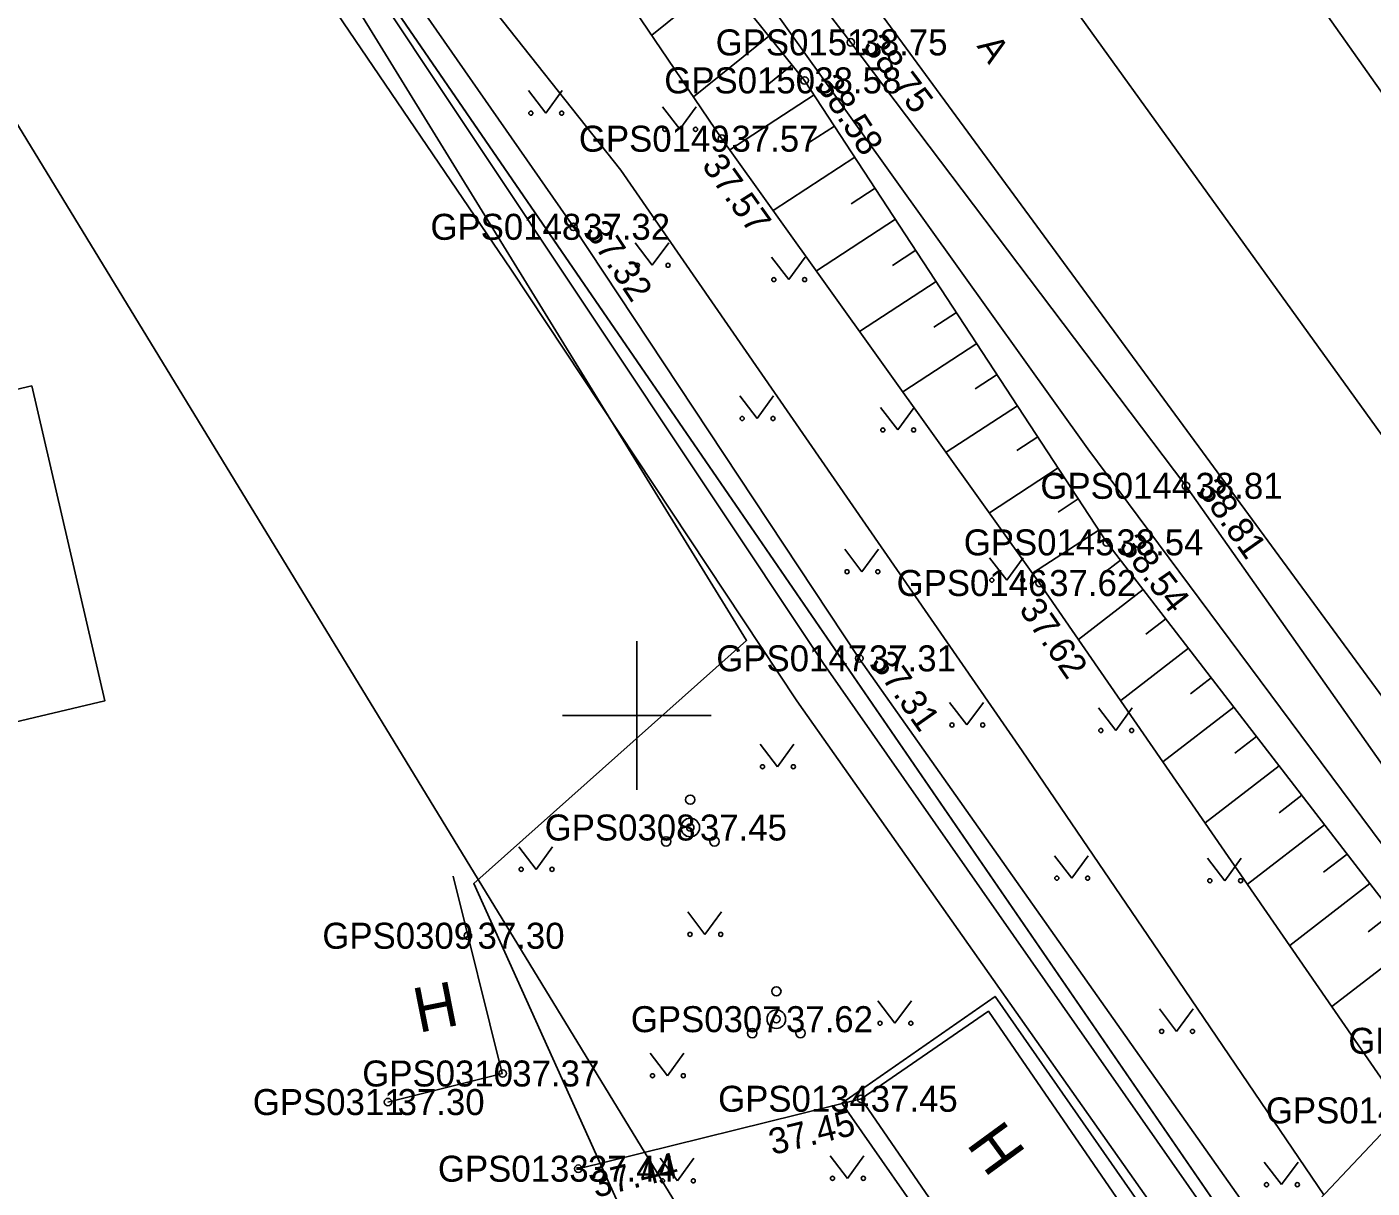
# Model space of a CAD drawing. Extents: x 626224 to 628280, y 6467750 to 6471135.
# Drawn here: x 627683.58 to 627719.8, y 6468587.27 to 6468618.54 of the extents above; entities that cross this region are included whole.
import ezdxf

# ---------------------------------------------------------------- set-up
doc = ezdxf.new("R2010")
doc.units = 0
for name, color, linetype in [('AED', 7, 'Continuous'), ('HALJASTUS', 7, 'Continuous'), ('HOONE', 7, 'Continuous'), ('Hoone Elu- või ühiskondlik hoone', 7, 'Continuous'), ('KORGUS-EH2000', 7, 'Continuous'), ('MOOTKORG-EH2000', 7, 'Continuous'), ('MOOTMPUNKT', 7, 'Continuous'), ('MOOTNR', 7, 'Continuous'), ('MOOTPIIR', 7, 'Continuous'), ('MPOHULIIN', 7, 'Continuous'), ('Muu rajatis Katusealune', 7, 'Continuous'), ('PIIR', 7, 'Continuous'), ('PUU', 7, 'Continuous'), ('RELJEEF', 7, 'Continuous'), ('SITRASS', 7, 'Continuous'), ('TEE', 7, 'Continuous'), ('Tee Liiklusala', 7, 'Continuous'), ('Tee Põhimaantee Püsikate', 7, 'Continuous'), ('VORK', 7, 'Continuous')]:
    doc.layers.add(name, color=color, linetype=linetype)

msp = doc.modelspace()

# ---------------------------------------------------------------- linework, layer by layer
at = {"layer": 'AED'}
msp.add_line((627706.037, 6468589.677), (627698.423, 6468587.794), dxfattribs=at)
at = {"layer": 'HALJASTUS'}
for p, q in [((627697.083, 6468616.826), (627697.547, 6468616.219)), ((627697.547, 6468616.219), (627697.992, 6468616.826)), ((627700.689, 6468616.392), (627701.153, 6468615.785)), ((627701.153, 6468615.785), (627701.598, 6468616.392)), ((627699.95, 6468612.729), (627700.413, 6468612.123)), ((627700.413, 6468612.123), (627700.859, 6468612.729)), ((627703.625, 6468612.345), (627704.088, 6468611.738)), ((627704.088, 6468611.738), (627704.534, 6468612.345)), ((627702.774, 6468608.603), (627703.237, 6468607.996)), ((627703.237, 6468607.996), (627703.683, 6468608.603)), ((627706.56, 6468608.297), (627707.024, 6468607.69)), ((627707.024, 6468607.69), (627707.469, 6468608.297)), ((627705.598, 6468604.477), (627706.061, 6468603.87)), ((627706.061, 6468603.87), (627706.507, 6468604.477)), ((627709.496, 6468604.249), (627709.959, 6468603.643)), ((627709.959, 6468603.643), (627710.405, 6468604.249)), ((627708.421, 6468600.351), (627708.885, 6468599.744)), ((627708.885, 6468599.744), (627709.33, 6468600.351)), ((627712.431, 6468600.202), (627712.895, 6468599.595)), ((627712.895, 6468599.595), (627713.34, 6468600.202)), ((627703.321, 6468599.226), (627703.784, 6468598.619)), ((627703.784, 6468598.619), (627704.23, 6468599.226)), ((627696.823, 6468596.463), (627697.286, 6468595.856)), ((627697.286, 6468595.856), (627697.732, 6468596.463)), ((627711.245, 6468596.224), (627711.709, 6468595.618)), ((627711.709, 6468595.618), (627712.154, 6468596.224)), ((627715.367, 6468596.154), (627715.83, 6468595.548)), ((627715.83, 6468595.548), (627716.276, 6468596.154)), ((627701.368, 6468594.711), (627701.831, 6468594.104)), ((627701.831, 6468594.104), (627702.277, 6468594.711)), ((627706.485, 6468592.319), (627706.949, 6468591.712)), ((627706.949, 6468591.712), (627707.394, 6468592.319)), ((627714.069, 6468592.098), (627714.533, 6468591.491)), ((627714.533, 6468591.491), (627714.978, 6468592.098)), ((627700.358, 6468590.904), (627700.821, 6468590.297)), ((627700.821, 6468590.297), (627701.267, 6468590.904)), ((627700.627, 6468588.074), (627701.091, 6468587.467)), ((627701.091, 6468587.467), (627701.536, 6468588.074)), ((627705.206, 6468588.141), (627705.669, 6468587.534)), ((627705.669, 6468587.534), (627706.115, 6468588.141)), ((627716.893, 6468587.972), (627717.356, 6468587.365)), ((627717.356, 6468587.365), (627717.802, 6468587.972))]:
    msp.add_line(p, q, dxfattribs=at)
for points in [[(627673.61, 6468619.969), (627672.976, 6468621.286), (627679.187, 6468622.456), (627687.969, 6468624.157), (627689.948, 6468620.551), (627692.796, 6468621.064), (627698.292, 6468613.159), (627705.989, 6468601.538), (627717.166, 6468585.678)], [(627716.572, 6468584.873), (627705.028, 6468601.396), (627692.406, 6468620.356), (627689.621, 6468619.759), (627687.703, 6468623.543), (627673.321, 6468620.739)], [(627673.61, 6468619.969), (627679.701, 6468621.092), (627687.315, 6468622.642), (627689.297, 6468618.889), (627691.61, 6468619.392), (627696.609, 6468612.017), (627704.309, 6468600.39), (627715.503, 6468584.506)]]:
    msp.add_lwpolyline(points, dxfattribs=at)
for centre in [(627697.146, 6468616.219), (627697.975, 6468616.219), (627700.752, 6468615.785), (627701.58, 6468615.785), (627700.012, 6468612.123), (627700.841, 6468612.123), (627703.687, 6468611.738), (627704.516, 6468611.738), (627702.836, 6468607.996), (627703.665, 6468607.996), (627706.623, 6468607.69), (627707.451, 6468607.69), (627705.66, 6468603.87), (627706.489, 6468603.87), (627709.558, 6468603.643), (627710.387, 6468603.643), (627708.484, 6468599.744), (627709.313, 6468599.744), (627712.494, 6468599.595), (627713.323, 6468599.595), (627703.383, 6468598.619), (627704.212, 6468598.619), (627696.885, 6468595.856), (627697.714, 6468595.856), (627711.308, 6468595.618), (627712.137, 6468595.618), (627715.429, 6468595.548), (627716.258, 6468595.548), (627701.43, 6468594.104), (627702.259, 6468594.104), (627706.548, 6468591.712), (627707.377, 6468591.712), (627714.132, 6468591.491), (627714.96, 6468591.491), (627700.42, 6468590.297), (627701.249, 6468590.297), (627705.268, 6468587.534), (627706.097, 6468587.534), (627700.69, 6468587.467), (627701.518, 6468587.467), (627716.955, 6468587.365), (627717.784, 6468587.365)]:
    msp.add_circle(centre, 0.055, dxfattribs=at)
at = {"layer": 'HOONE'}
for p, q in [((627695.051, 6468595.673), (627696.376, 6468590.356)), ((627693.298, 6468589.589), (627696.386, 6468590.358))]:
    msp.add_line(p, q, dxfattribs=at)
msp.add_lwpolyline([(627706.037, 6468589.677), (627709.589, 6468584.515), (627713.017, 6468586.873), (627709.466, 6468592.035)], close=True, dxfattribs=at)
at = {"layer": 'Hoone Elu- või ühiskondlik hoone'}
msp.add_lwpolyline([(627678.585, 6468598.716), (627677.114, 6468604.925), (627668.925, 6468602.995), (627666.971, 6468610.855), (627681.171, 6468614.225), (627682.555, 6468608.606), (627683.705, 6468608.876), (627685.675, 6468600.395)], close=True, dxfattribs=at)
at = {"layer": 'KORGUS-EH2000'}
for centre in [(627705.762, 6468618.126), (627704.517, 6468617.101), (627702.288, 6468615.532), (627698.292, 6468613.159), (627714.785, 6468606.184), (627712.652, 6468604.661), (627710.843, 6468603.567), (627705.989, 6468601.538), (627701.438, 6468596.982), (627703.756, 6468591.821), (627696.386, 6468590.358), (627706.037, 6468589.677), (627698.423, 6468587.794)]:
    msp.add_circle(centre, 0.1, dxfattribs=at)
at = {"layer": 'MOOTMPUNKT'}
for centre in [(627705.762, 6468618.126), (627704.517, 6468617.101), (627702.288, 6468615.532), (627698.292, 6468613.159), (627714.785, 6468606.184), (627712.652, 6468604.661), (627710.843, 6468603.567), (627705.989, 6468601.538), (627701.438, 6468596.982), (627695.451, 6468594.068), (627703.756, 6468591.821), (627696.386, 6468590.358), (627706.037, 6468589.677), (627693.298, 6468589.589), (627698.423, 6468587.794)]:
    msp.add_circle(centre, 0.1, dxfattribs=at)
at = {"layer": 'MOOTPIIR'}
for points in [[(627725.17, 6468593.561), (627699.891, 6468628.007), (627691.556, 6468636.216), (627689.682, 6468635.294), (627688.429, 6468634.933), (627687.779, 6468636.161), (627663.981, 6468631.653), (627656.533, 6468628.521), (627633.238, 6468625.152)], [(627644.92, 6468614.927), (627687.389, 6468622.904), (627689.377, 6468619.311), (627692.038, 6468619.76), (627702.956, 6468602.021), (627695.606, 6468595.477), (627701.992, 6468581.333), (627711.232, 6468581.738), (627717.166, 6468585.678), (627720.646, 6468589.364)]]:
    msp.add_lwpolyline(points, dxfattribs=at)
at = {"layer": 'MPOHULIIN'}
for points in [[(627695.728, 6468595.585), (627679.915, 6468621.5)], [(627704.355, 6468581.436), (627701.716, 6468585.772), (627695.728, 6468595.585)]]:
    msp.add_lwpolyline(points, dxfattribs=at)
at = {"layer": 'Muu rajatis Katusealune'}
msp.add_lwpolyline([(627705.521, 6468589.562), (627709.645, 6468592.435), (627715.151, 6468584.531), (627711.028, 6468581.659)], close=True, dxfattribs=at)
at = {"layer": 'PIIR'}
msp.add_lwpolyline([(627746.91, 6468541.23), (627688.18, 6468626.77), (627684.35, 6468632.16), (627686.69, 6468632.75), (627663.66, 6468662.2), (627667.34, 6468664.86), (627649.05, 6468692.73), (627646.31, 6468691.19), (627629.12, 6468721.76), (627618.92, 6468715.04), (627606.91, 6468724.16), (627579.16, 6468687.58), (627549.96, 6468707.41), (627588.77, 6468756.22), (627618.05, 6468733.86), (627619.84, 6468735.06), (627604.18, 6468764.29), (627579.83, 6468812.09), (627559.2, 6468856.67), (627547.01, 6468886.57), (627533.67, 6468925.79), (627531.86, 6468935.62), (627512.37, 6469002.4)], dxfattribs=at)
msp.add_lwpolyline([(627746.91, 6468541.23), (627666.94, 6468517.08), (627653, 6468577.43), (627643.52, 6468618.24), (627688.18, 6468626.77)], close=True, dxfattribs=at)
at = {"layer": 'PUU'}
for centre, radius in [((627701.438, 6468597.732), 0.125), ((627701.438, 6468596.982), 0.25), ((627700.788, 6468596.607), 0.125), ((627702.088, 6468596.607), 0.125), ((627703.756, 6468592.571), 0.125), ((627703.756, 6468591.821), 0.25), ((627703.106, 6468591.446), 0.125), ((627704.406, 6468591.446), 0.125)]:
    msp.add_circle(centre, radius, dxfattribs=at)
at = {"layer": 'RELJEEF'}
for p, q in [((627702.302, 6468619.854), (627700.399, 6468618.322)), ((627703.556, 6468618.296), (627701.524, 6468616.66)), ((627704.183, 6468617.517), (627703.554, 6468617.011)), ((627704.773, 6468616.711), (627702.506, 6468615.228)), ((627705.32, 6468615.874), (627704.65, 6468615.436)), ((627705.868, 6468615.037), (627703.67, 6468613.6)), ((627706.415, 6468614.2), (627705.766, 6468613.776)), ((627706.962, 6468613.363), (627704.834, 6468611.972)), ((627707.509, 6468612.526), (627706.881, 6468612.115)), ((627708.057, 6468611.689), (627705.998, 6468610.343)), ((627708.604, 6468610.852), (627707.997, 6468610.455)), ((627709.151, 6468610.015), (627707.163, 6468608.715)), ((627709.698, 6468609.178), (627709.112, 6468608.795)), ((627710.246, 6468608.341), (627708.327, 6468607.087)), ((627710.793, 6468607.504), (627710.228, 6468607.135)), ((627711.34, 6468606.667), (627709.491, 6468605.458)), ((627711.887, 6468605.83), (627711.343, 6468605.474)), ((627712.435, 6468604.993), (627710.655, 6468603.83)), ((627713.02, 6468604.183), (627712.511, 6468603.79)), ((627713.631, 6468603.392), (627711.891, 6468602.049)), ((627714.242, 6468602.6), (627713.707, 6468602.188)), ((627714.853, 6468601.808), (627713.029, 6468600.401)), ((627715.464, 6468601.016), (627714.904, 6468600.585)), ((627716.074, 6468600.225), (627714.166, 6468598.753)), ((627716.685, 6468599.433), (627716.1, 6468598.982)), ((627717.296, 6468598.641), (627715.304, 6468597.104)), ((627717.907, 6468597.849), (627717.297, 6468597.379)), ((627718.518, 6468597.058), (627716.442, 6468595.456)), ((627719.129, 6468596.266), (627718.493, 6468595.776)), ((627719.739, 6468595.474), (627717.579, 6468593.808)), ((627720.35, 6468594.682), (627719.69, 6468594.173)), ((627720.961, 6468593.891), (627718.717, 6468592.159))]:
    msp.add_line(p, q, dxfattribs=at)
for points in [[(627664.293, 6468620.969), (627678.559, 6468624.205), (627686.866, 6468625.972), (627692.626, 6468627.53), (627694.391, 6468627.395), (627696.02, 6468626.757), (627697.766, 6468625.488), (627704.517, 6468617.101), (627712.652, 6468604.661), (627723.007, 6468591.238)], [(627664.284, 6468620.85), (627678.877, 6468623.378), (627691.199, 6468626.166), (627693.024, 6468626.089), (627694.96, 6468625.086), (627696.853, 6468623.559), (627702.288, 6468615.532), (627710.843, 6468603.567), (627720.646, 6468589.364)]]:
    msp.add_lwpolyline(points, dxfattribs=at)
at = {"layer": 'SITRASS'}
msp.add_lwpolyline([(627718.499, 6468587.089), (627713.907, 6468593.848), (627710.374, 6468599.048), (627699.564, 6468614.681), (627695.628, 6468619.665), (627689.767, 6468629.543), (627685.369, 6468635.281)], dxfattribs=at)
at = {"layer": 'TEE'}
msp.add_lwpolyline([(627691.556, 6468636.216), (627691.411, 6468633.572), (627690.377, 6468632.362), (627688.302, 6468631.311), (627683.705, 6468630.285), (627675.534, 6468628.326), (627664.963, 6468626.349), (627655.323, 6468624.553), (627656.855, 6468621.064), (627660.849, 6468621.603), (627663.795, 6468622.181), (627671.677, 6468623.939), (627678.512, 6468625.342), (627686.437, 6468627.071), (627694.212, 6468628.779), (627696.498, 6468628.635), (627697.947, 6468628.287), (627705.762, 6468618.126), (627714.785, 6468606.184), (627724.497, 6468592.392)], dxfattribs=at)
at = {"layer": 'Tee Liiklusala'}
for points in [[(627542.306, 6468967.371), (627548.71, 6468942.84), (627554.3, 6468925.9), (627578.18, 6468861.63), (627588.31, 6468840.05), (627629.52, 6468759.1), (627656.29, 6468714.41), (627663.537, 6468702.423), (627687.78, 6468662.54), (627695.93, 6468652.611), (627708.93, 6468632.54), (627721.86, 6468614.22), (627748.47, 6468578.42), (627760.92, 6468560.36), (627780.56, 6468531.91)], [(627770.48, 6468525.39), (627740.557, 6468568.764), (627738.71, 6468571.44), (627735.13, 6468576.26), (627712.14, 6468607.18), (627694.794, 6468631.457), (627678.044, 6468653.167), (627666.826, 6468668.407), (627651.484, 6468693.118), (627649.736, 6468695.878), (627641.743, 6468708.498), (627640.999, 6468709.875), (627623.478, 6468742.312), (627616.983, 6468754.336), (627595.384, 6468797.487), (627592.828, 6468802.833), (627577.59, 6468834.7), (627567.06, 6468857.03), (627562.51, 6468869.71), (627561.06, 6468873.68), (627543.04, 6468921.76), (627539.249, 6468933.164), (627537.18, 6468939.44), (627530.65, 6468964.53)]]:
    msp.add_lwpolyline(points, dxfattribs=at)
at = {"layer": 'Tee Põhimaantee Püsikate'}
msp.add_lwpolyline([(627700.902, 6468634.138), (627743.449, 6468575.098), (627775.098, 6468528.301), (627799.448, 6468490.206), (627812.119, 6468468.847)], dxfattribs=at)
at = {"layer": 'VORK'}
for p, q in [((627700, 6468602), (627700, 6468598)), ((627698, 6468600), (627702, 6468600))]:
    msp.add_line(p, q, dxfattribs=at)

# ---------------------------------------------------------------- texts
at = {"layer": 'HOONE'}
for rotation, p in [(11.209, (627694.123, 6468591.45)), (306.1592, (627708.852, 6468588.456))]:
    msp.add_text('H', height=1.2, rotation=rotation, dxfattribs=at).set_placement(p)
at = {"layer": 'KORGUS-EH2000'}
for s, rotation, p in [(' 38.75', 307.0746, (627705.901, 6468618.231)), (' 38.58', 303.1788, (627704.664, 6468617.197)), (' 37.57', 305.5651, (627701.577, 6468615.023)), (' 37.32', 303.5169, (627698.438, 6468613.256)), (' 38.81', 305.153, (627714.928, 6468606.284)), (' 38.54', 307.6506, (627712.791, 6468604.767)), (' 37.62', 304.6141, (627710.123, 6468603.07)), (' 37.31', 305.1726, (627706.132, 6468601.639)), (' 37.45', 13.886, (627703.4, 6468588.097)), (' 37.44', 13.886, (627698.633, 6468586.945))]:
    msp.add_text(s, height=0.7, rotation=rotation, dxfattribs=at).set_placement(p)
for s, p in [(' 37.45', (627701.438, 6468596.632)), (' 37.62', (627703.756, 6468591.471)), (' 37.37', (627696.386, 6468590.008))]:
    msp.add_text(s, height=0.7, dxfattribs=at).set_placement(p)
at = {"layer": 'MOOTKORG-EH2000'}
for s, p in [(' 38.75', (627705.762, 6468617.775)), (' 38.58', (627704.517, 6468616.752)), (' 37.57', (627702.288, 6468615.182)), (' 37.32', (627698.292, 6468612.809)), (' 38.81', (627714.785, 6468605.834)), (' 38.54', (627712.652, 6468604.311)), (' 37.62', (627710.843, 6468603.217)), (' 37.31', (627705.989, 6468601.188)), (' 37.45', (627701.438, 6468596.632)), (' 37.30', (627695.451, 6468593.718)), (' 37.62', (627703.756, 6468591.471)), (' 37.37', (627696.386, 6468590.008)), (' 37.30', (627693.298, 6468589.239)), (' 37.45', (627706.037, 6468589.327)), (' 37.44', (627698.423, 6468587.444))]:
    msp.add_text(s, height=0.7, dxfattribs=at).set_placement(p)
at = {"layer": 'MOOTNR'}
for s, p in [('GPS0151 ', (627702.122, 6468617.775)), ('GPS0150 ', (627700.738, 6468616.752)), ('GPS0149 ', (627698.439, 6468615.182)), ('GPS0148 ', (627694.442, 6468612.809)), ('GPS0144 ', (627710.865, 6468605.834)), ('GPS0145 ', (627708.802, 6468604.311)), ('GPS0146 ', (627706.994, 6468603.217)), ('GPS0147 ', (627702.139, 6468601.188)), ('GPS0308 ', (627697.518, 6468596.632)), ('GPS0309 ', (627691.531, 6468593.718)), ('GPS0307 ', (627699.837, 6468591.471)), ('GPS0142 ', (627719.158, 6468590.888)), ('GPS0310 ', (627692.606, 6468590.008)), ('GPS0311 ', (627689.658, 6468589.239)), ('GPS0134 ', (627702.188, 6468589.327)), ('GPS0141 ', (627716.937, 6468589.014)), ('GPS0133 ', (627694.643, 6468587.444))]:
    msp.add_text(s, height=0.7, dxfattribs=at).set_placement(p)
at = {"layer": 'TEE'}
msp.add_text('A', height=0.7, rotation=304.0922, dxfattribs=at).set_placement((627709.138, 6468618.026))

doc.saveas('drawing.dxf')
